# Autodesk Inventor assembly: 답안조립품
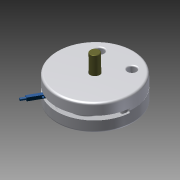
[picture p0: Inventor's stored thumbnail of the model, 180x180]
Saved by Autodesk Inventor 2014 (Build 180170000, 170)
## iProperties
Created: 2015-05
Part Number: 답안조립품
Document SubType Name: Assembly
Designer: USER
Author: USER
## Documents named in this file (10)
- C:\Users\USER\Desktop\Inventor2급-이민광\답안조립품.iam
- C:\Users\USER\Desktop\Inventor2급-이민광\본체.ipt
- C:\Users\USER\Desktop\Inventor2급-이민광\베어링62_22.ipt
- C:\Users\USER\Desktop\Inventor2급-이민광\축.ipt
- C:\Users\USER\Desktop\Inventor2급-이민광\멈춤링.ipt
- C:\Users\USER\Desktop\Inventor2급-이민광\덮개.ipt
- C:\Users\USER\Desktop\Inventor2급-이민광\슬라이더2.ipt
- C:\Users\USER\Desktop\Inventor2급-이민광\슬라이더.ipt
- C:\Users\USER\Desktop\Inventor2급-이민광\평행핀.ipt
- C:\Users\USER\Desktop\Inventor2급-이민광\M 10 x 35.ipt
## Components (2 placed, 1 different names)
1. M 10 x 35:1
2. M 10 x 35:2
